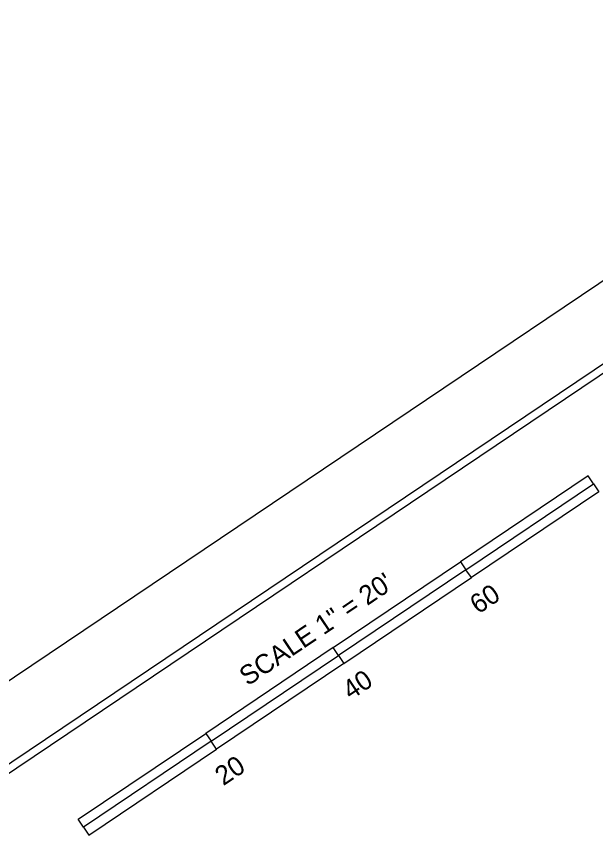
# Model space of a CAD drawing. Extents: x 1439200 to 1640973, y 392611 to 606444.
# Drawn here: x 1640517 to 1640592.4, y 393189.2 to 393296.5 of the extents above; entities that cross this region are included whole.
import ezdxf

# ---------------------------------------------------------------- set-up
doc = ezdxf.new("R2010")
doc.units = 0
for name, color, linetype in [('Old_Level_20', 7, 'Continuous'), ('Sheet Plot Border Inside CELL', 7, 'Continuous'), ('Sheet Plot Border Outside CELL', 7, 'Continuous'), ('UC Plan Sheet 34 CELL', 7, 'Continuous')]:
    doc.layers.add(name, color=color, linetype=linetype)

msp = doc.modelspace()

# ---------------------------------------------------------------- linework, layer by layer
at = {"layer": 'Old_Level_20'}
for points in [[(1640575.54, 393224.48), (1640592.14, 393235.65), (1640591.44, 393236.69), (1640574.84, 393225.52), (1640575.54, 393224.48)], [(1640559.65, 393212.28), (1640576.24, 393223.45), (1640575.54, 393224.48), (1640558.95, 393213.32), (1640559.65, 393212.28)], [(1640542.35, 393202.16), (1640558.95, 393213.32), (1640558.25, 393214.36), (1640541.66, 393203.19), (1640542.35, 393202.16)], [(1640526.46, 393189.95), (1640543.05, 393201.12), (1640542.35, 393202.16), (1640525.76, 393190.99), (1640526.46, 393189.95)]]:
    msp.add_lwpolyline(points, dxfattribs=at)
for points in [[(1640575.54, 393224.48), (1640592.14, 393235.65), (1640592.83, 393234.61), (1640576.24, 393223.45)], [(1640558.25, 393214.36), (1640574.84, 393225.52), (1640575.54, 393224.48), (1640558.95, 393213.32)], [(1640542.35, 393202.16), (1640558.95, 393213.32), (1640559.65, 393212.28), (1640543.05, 393201.12)], [(1640525.06, 393192.03), (1640541.66, 393203.19), (1640542.35, 393202.16), (1640525.76, 393190.99)]]:
    msp.add_lwpolyline(points, close=True, dxfattribs=at)
at = {"layer": 'Sheet Plot Border Inside CELL'}
msp.add_lwpolyline([(1640730.44, 393343.49), (1640177.37, 392971.37), (1640412.97, 392621.21), (1640966.04, 392993.34)], close=True, dxfattribs=at)
at = {"layer": 'Sheet Plot Border Outside CELL'}
msp.add_lwpolyline([(1640726.92, 393351.95), (1640168.05, 392975.92), (1640413.67, 392610.86), (1640972.54, 392986.89)], close=True, dxfattribs=at)
at = {"layer": 'UC Plan Sheet 34 CELL'}
msp.add_lwpolyline([(1640726.86, 393339.86), (1640229.05, 393004.91), (1640463.51, 392656.45), (1640961.32, 392991.39)], close=True, dxfattribs=at)

# ---------------------------------------------------------------- texts
at = {"layer": 'Old_Level_20'}
for s, p in [('SCALE 1" = 20\'', (1640547.12, 393209.28)), ('60', (1640577.14, 393218.63)), ('40', (1640560.55, 393207.47)), ('20', (1640543.95, 393196.3))]:
    msp.add_text(s, height=2.5, rotation=33.9342, dxfattribs=at).set_placement(p)

doc.saveas('drawing.dxf')
